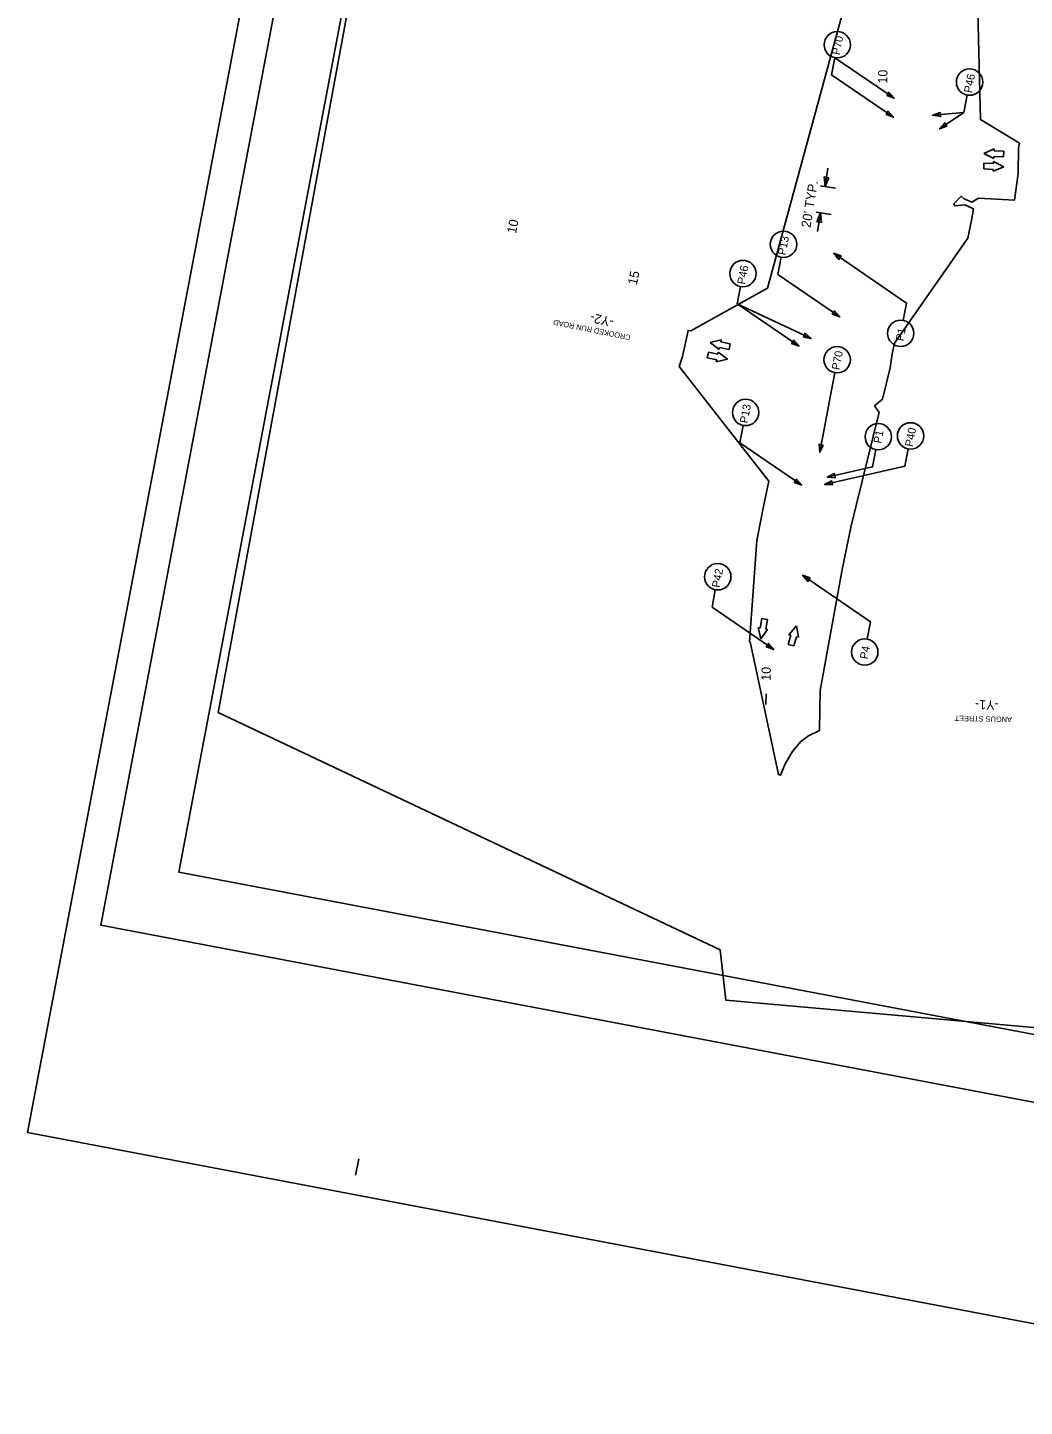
# Model space of a CAD drawing. Extents: x 1615680 to 1619687, y 899305 to 902270.
# Drawn here: x 1615680 to 1616427, y 899305 to 900338 of the extents above; entities that cross this region are included whole.
import ezdxf

# ---------------------------------------------------------------- set-up
doc = ezdxf.new("R2010")
doc.units = 0
for name, color, linetype in [('Default', 7, 'Continuous'), ('DEV STATIONARY SIGN CELL', 7, 'Continuous'), ('Prop Conc 2ft 6in Curb and Gutter', 7, 'Continuous'), ('Prop Conc 4in Sidewalk', 7, 'Continuous'), ('Prop Conc 5in Monolithic Keyed In Island', 7, 'Continuous'), ('Prop Conc Valley Gutter', 7, 'Continuous'), ('Prop Mkg Solid Yel Skip RT Rpm 80ft', 7, 'Continuous'), ('Scratch_Level_7', 7, 'Continuous'), ('Scratch_Level_8', 7, 'Continuous'), ('Stage 5', 7, 'Continuous')]:
    doc.layers.add(name, color=color, linetype=linetype)

msp = doc.modelspace()

# ---------------------------------------------------------------- linework, layer by layer
at = {"layer": 'Default'}
for p, q in [((1616284.8, 900315.8), (1616329.2, 900285.4)), ((1616381.4, 900274.8), (1616363.2, 900262.4)), ((1616211.6, 900131.3), (1616267.1, 900105.3))]:
    msp.add_line(p, q, dxfattribs=at)
for points in [[(1616284.8, 900315.8), (1616282.3, 900302.9), (1616328.7, 900271.1)], [(1616383.8, 900287.8), (1616381.4, 900274.8), (1616358.1, 900272.6)], [(1616244.5, 900166.2), (1616242, 900153.3), (1616288.4, 900121.5)], [(1616336, 900118.9), (1616338.4, 900131.9), (1616283.9, 900169.2)], [(1616214.1, 900144.3), (1616211.6, 900131.3), (1616258, 900099.6)], [(1616284.7, 900079.7), (1616282.2, 900066.7), (1616273.4, 900020)], [(1616216, 900040.2), (1616213.6, 900027.2), (1616260, 899995.5)], [(1616339.7, 900022.5), (1616337.2, 900009.6), (1616277.1, 899995.8)], [(1616315.4, 900022), (1616313, 900009), (1616279.1, 900001.3)], [(1616309.1, 899880.1), (1616311.5, 899893), (1616260.6, 899927.9)], [(1616195.1, 899916.9), (1616192.7, 899904), (1616239, 899872.2)]]:
    msp.add_lwpolyline(points, dxfattribs=at)
for points in [[(1616323.6, 900287.4), (1616329.2, 900285.4), (1616325.3, 900289.9)], [(1616323.1, 900273.1), (1616328.7, 900271.1), (1616324.8, 900275.6)], [(1616364.1, 900271.6), (1616358.1, 900272.6), (1616363.8, 900274.7)], [(1616368.8, 900264.4), (1616363.2, 900262.4), (1616367.1, 900267)], [(1616289.6, 900167.2), (1616283.9, 900169.2), (1616287.8, 900164.6)], [(1616282.8, 900123.5), (1616288.4, 900121.5), (1616284.5, 900126)], [(1616261.2, 900106.4), (1616267.1, 900105.3), (1616262.5, 900109.2)], [(1616252.4, 900101.6), (1616258, 900099.6), (1616254.1, 900104.1)], [(1616276, 900025.4), (1616273.4, 900020), (1616273, 900026)], [(1616254.3, 899997.5), (1616260, 899995.5), (1616256.1, 900000)], [(1616283.1, 899995.6), (1616277.1, 899995.8), (1616282.4, 899998.6)], [(1616285.1, 900001), (1616279.1, 900001.3), (1616284.4, 900004.1)], [(1616266.3, 899925.9), (1616260.6, 899927.9), (1616264.5, 899923.3)], [(1616233.4, 899874.2), (1616239, 899872.2), (1616235.1, 899876.8)]]:
    msp.add_lwpolyline(points, close=True, dxfattribs=at)
for centre in [(1616286.6, 900325.5), (1616385.7, 900297.5), (1616246.3, 900175.9), (1616215.9, 900154), (1616334.1, 900109.2), (1616286.5, 900089.4), (1616217.9, 900049.9), (1616317.3, 900031.7), (1616341.5, 900032.3), (1616197, 899926.7), (1616307.2, 899870.3)]:
    msp.add_circle(centre, 9.89, dxfattribs=at)
at = {"layer": 'DEV STATIONARY SIGN CELL'}
msp.add_line((1616233.1, 899831), (1616233.2, 899839), dxfattribs=at)
at = {"layer": 'Prop Conc 4in Sidewalk'}
msp.add_lwpolyline([(1616176.3, 901060.7), (1616848.5, 900914.3), (1616896.3, 900812.9), (1616872.9, 900688.2), (1616835.9, 900695.2), (1616753.9, 900262.2), (1616898.1, 900233.4), (1616734.8, 899562.1), (1616203, 899609.4), (1616198.7, 899647.1), (1615822.7, 899825.1), (1616054.3, 901080.8)], close=True, dxfattribs=at)
at = {"layer": 'Prop Conc 5in Monolithic Keyed In Island'}
for p, q in [((1616404.2, 900247.5), (1616396.3, 900244.1)), ((1616396.3, 900244.1), (1616404.2, 900247.5)), ((1616396.3, 900244.1), (1616404, 900240.2)), ((1616404, 900240.2), (1616396.3, 900244.1)), ((1616404.2, 900246), (1616404.2, 900247.5)), ((1616404.2, 900247.5), (1616404.2, 900246)), ((1616411.4, 900245.8), (1616404.2, 900246)), ((1616404.2, 900246), (1616411.4, 900245.8)), ((1616411.2, 900241.5), (1616411.4, 900245.8)), ((1616411.4, 900245.8), (1616411.2, 900241.5)), ((1616396.4, 900236.7), (1616396.3, 900232.4)), ((1616396.3, 900232.4), (1616396.4, 900236.7)), ((1616396.3, 900232.4), (1616403.5, 900232.1)), ((1616403.5, 900232.1), (1616396.3, 900232.4)), ((1616403.6, 900236.5), (1616396.4, 900236.7)), ((1616396.4, 900236.7), (1616403.6, 900236.5)), ((1616403.5, 900230.7), (1616411.3, 900234.1)), ((1616411.3, 900234.1), (1616403.5, 900230.7)), ((1616403.5, 900232.1), (1616403.5, 900230.7)), ((1616403.5, 900230.7), (1616403.5, 900232.1)), ((1616403.7, 900238), (1616403.6, 900236.5)), ((1616403.6, 900236.5), (1616403.7, 900238)), ((1616411.3, 900234.1), (1616403.7, 900238)), ((1616403.7, 900238), (1616411.3, 900234.1)), ((1616404, 900240.2), (1616404, 900241.7)), ((1616404, 900241.7), (1616411.2, 900241.5)), ((1616411.2, 900241.5), (1616404, 900241.7)), ((1616404, 900241.7), (1616404, 900240.2)), ((1616199.6, 900104.3), (1616191.3, 900102.3)), ((1616191.3, 900102.3), (1616199.6, 900104.3)), ((1616191.3, 900102.3), (1616198.1, 900097.1)), ((1616198.1, 900097.1), (1616191.3, 900102.3)), ((1616198.1, 900097.1), (1616198.4, 900098.6)), ((1616198.4, 900098.6), (1616198.1, 900097.1)), ((1616198.4, 900098.6), (1616205.5, 900097.1)), ((1616205.5, 900097.1), (1616198.4, 900098.6)), ((1616199.3, 900102.8), (1616199.6, 900104.3)), ((1616199.6, 900104.3), (1616199.3, 900102.8)), ((1616206.4, 900101.3), (1616199.3, 900102.8)), ((1616199.3, 900102.8), (1616206.4, 900101.3)), ((1616205.5, 900097.1), (1616206.4, 900101.3)), ((1616206.4, 900101.3), (1616205.5, 900097.1)), ((1616190.1, 900095), (1616189.2, 900090.8)), ((1616189.2, 900090.8), (1616190.1, 900095)), ((1616189.2, 900090.8), (1616196.2, 900089.3)), ((1616196.2, 900089.3), (1616189.2, 900090.8)), ((1616197.1, 900093.5), (1616190.1, 900095)), ((1616190.1, 900095), (1616197.1, 900093.5)), ((1616195.9, 900087.8), (1616204.2, 900089.8)), ((1616204.2, 900089.8), (1616195.9, 900087.8)), ((1616196.2, 900089.3), (1616195.9, 900087.8)), ((1616195.9, 900087.8), (1616196.2, 900089.3)), ((1616197.4, 900095), (1616197.1, 900093.5)), ((1616197.1, 900093.5), (1616197.4, 900095)), ((1616204.2, 900089.8), (1616197.4, 900095)), ((1616197.4, 900095), (1616204.2, 900089.8)), ((1616230, 899895.4), (1616228.7, 899888.3)), ((1616234.3, 899894.6), (1616230, 899895.4)), ((1616233, 899887.5), (1616234.3, 899894.6)), ((1616228.7, 899888.3), (1616227.2, 899888.6)), ((1616227.2, 899888.6), (1616229.4, 899880.3)), ((1616229.4, 899880.3), (1616234.4, 899887.2)), ((1616234.4, 899887.2), (1616233, 899887.5)), ((1616251.8, 899882.9), (1616249.9, 899876)), ((1616255.9, 899889.9), (1616250.4, 899883.3)), ((1616250.4, 899883.3), (1616251.8, 899882.9)), ((1616254.1, 899874.9), (1616256, 899881.8)), ((1616257.4, 899881.4), (1616255.9, 899889.9)), ((1616256, 899881.8), (1616257.4, 899881.4)), ((1616249.9, 899876), (1616254.1, 899874.9))]:
    msp.add_line(p, q, dxfattribs=at)
at = {"layer": 'Prop Conc Valley Gutter'}
for points in [[(1616273.8, 899841.4), (1616273.2, 899812.2), (1616273.2, 899811.4), (1616265, 899807.4), (1616259, 899802.9), (1616253.1, 899795.7), (1616247.5, 899786.6), (1616244, 899777.9), (1616242.5, 899778.4), (1616221.3, 899877.9), (1616220.9, 899877.9), (1616226.3, 899953.8), (1616231.4, 899979.3), (1616235.4, 899998.5), (1616168.2, 900084.4), (1616170.5, 900091.8), (1616174.8, 900111.4), (1616176.8, 900111), (1616234.2, 900143.1), (1616336.3, 900517.1), (1616337.6, 900527.6), (1616345.4, 900547.7), (1616347.7, 900556.9), (1616364.1, 900697.8)], [(1616392, 900350.4), (1616393.9, 900269.4), (1616423.1, 900251.6), (1616422.5, 900248.3), (1616422.2, 900229.1), (1616419.5, 900209), (1616392.3, 900210.6), (1616387.3, 900207.6), (1616381.6, 900210), (1616379.4, 900211.9), (1616373.9, 900206.3), (1616374.7, 900204.8), (1616382.3, 900205.4), (1616388.7, 900202.4), (1616387.2, 900193.9), (1616384.3, 900180.4), (1616329.4, 900101.8), (1616327.7, 900093.8), (1616326.1, 900083.4), (1616320.5, 900059.9), (1616314.6, 900054.8), (1616318, 900049.9), (1616317.5, 900048.2), (1616297.1, 899964.8), (1616290.3, 899932.2), (1616273.8, 899841.4)]]:
    msp.add_lwpolyline(points, dxfattribs=at)
at = {"layer": 'Prop Mkg Solid Yel Skip RT Rpm 80ft'}
for p, q in [((1616279.6, 900233), (1616277.4, 900219.2)), ((1616285.2, 900217.9), (1616273.9, 900219.8)), ((1616281.9, 900198.2), (1616270.7, 900200)), ((1616274.1, 900199.5), (1616271.8, 900185.6))]:
    msp.add_line(p, q, dxfattribs=at)
for points in [[(1616280.2, 900225.8), (1616277.4, 900219.2), (1616276.8, 900226.4)], [(1616271.3, 900192.8), (1616274.1, 900199.5), (1616274.7, 900192.3)]]:
    msp.add_lwpolyline(points, close=True, dxfattribs=at)
at = {"layer": 'Scratch_Level_7'}
for p, q in [((1615734.9, 899666.5), (1615734.9, 899666.5)), ((1615925.6, 899478.1), (1615928, 899490.4))]:
    msp.add_line(p, q, dxfattribs=at)
msp.add_lwpolyline([(1616014.5, 901139.2), (1615734.7, 899665.5), (1616766.3, 899469.7), (1617046.1, 900943.3)], close=True, dxfattribs=at)
at = {"layer": 'Scratch_Level_8'}
msp.add_lwpolyline([(1616054.3, 901080.8), (1615793.2, 899705.3), (1616726.5, 899528.1), (1616890.5, 900391.5), (1616774.3, 900413.6), (1616871.5, 900925.6)], close=True, dxfattribs=at)
at = {"layer": 'Stage 5'}
for points in [[(1616760.5, 899304.9), (1615679.8, 899510.1), (1615994.7, 901168.4), (1617075.3, 900963.2)], [(1616760.5, 899304.9), (1617075.3, 900963.2), (1615994.7, 901168.4), (1615679.8, 899510.1)]]:
    msp.add_lwpolyline(points, close=True, dxfattribs=at)

# ---------------------------------------------------------------- texts
at = {"layer": 'Default'}
for s, height, rotation, p in [('P70', 6, 79.2494, (1616288.4, 900317.5)), ('P46', 6, 79.2494, (1616387.3, 900289)), ('P13', 6, 79.2493, (1616247.8, 900167.4)), ('P46', 6, 79.2493, (1616217.4, 900145.5)), ('CROOKED RUN ROAD', 4, 168.458, (1616132, 900107.8)), ('P1', 6, 79.2493, (1616336.2, 900103)), ('P70', 6, 79.2494, (1616288.2, 900081.4)), ('P13', 6, 79.2493, (1616219.3, 900041.4)), ('P1', 6, 79.2494, (1616319.5, 900026.3)), ('P40', 6, 79.2494, (1616343.1, 900023.8)), ('P42', 6, 79.2493, (1616198.4, 899918.2)), ('P4', 6, 79.2493, (1616309.3, 899864.6)), ('ANGUS STREET', 4, 178.7509, (1616417.5, 899821.7))]:
    msp.add_text(s, height=height, rotation=rotation, dxfattribs=at).set_placement(p)
at = {"layer": 'Prop Conc 2ft 6in Curb and Gutter'}
for s, rotation, p in [('10', 88.5681, (1616324, 900296.3)), ('10', 78.8364, (1616045.8, 900183.6)), ('15', 77.7098, (1616136.3, 900145)), ('-Y2-', 167.14, (1616119.6, 900120.6)), ('10', 88.5681, (1616236.6, 899848.7)), ('-Y1-', 179.3469, (1616407.6, 899834.1))]:
    msp.add_text(s, height=7, rotation=rotation, dxfattribs=at).set_placement(p)
at = {"layer": 'Prop Mkg Solid Yel Skip RT Rpm 80ft'}
msp.add_text("20' TYP.", height=7, rotation=80.6346, dxfattribs=at).set_placement((1616266.4, 900188))

doc.saveas('drawing.dxf')
